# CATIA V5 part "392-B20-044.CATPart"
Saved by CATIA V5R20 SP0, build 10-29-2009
Part number: 392-B20-044
Definition: NONE
Nomenclature: 392-B20-044
Source: Unknown
Description: 392-B20-044
Bounding box of the stored display mesh (mm): x 0 to 44, y -9.278 to 9.278, z -9.2 to 9.2
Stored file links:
  C:\Users\Utente\Desktop\IO LAVORO\3D X SITO CF\X SITO\3D files 392B\392-B20-044.CATPart
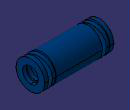
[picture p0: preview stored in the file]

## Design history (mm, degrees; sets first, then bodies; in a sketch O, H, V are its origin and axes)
Body1 "392-B20-044" (main body)
  Solid1: solid without history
